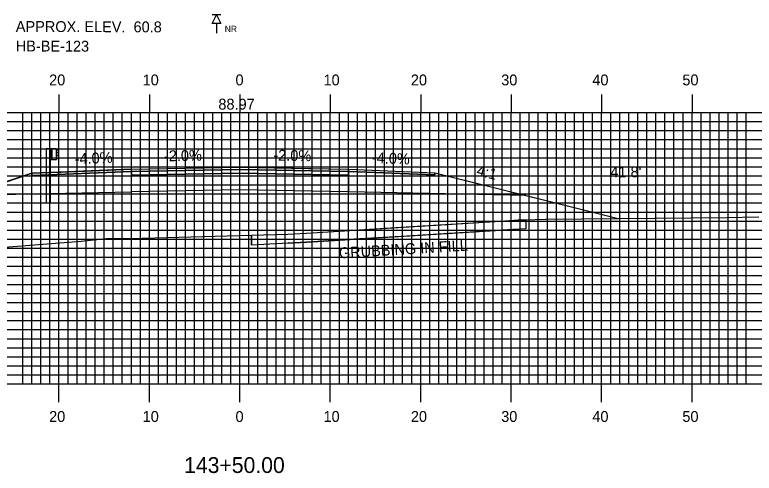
# Model space of a CAD drawing. Extents: x 1777138 to 1777481, y 442591 to 442811.
# Drawn here: x 1777278.9 to 1777360.6, y 442648.8 to 442699.5 of the extents above; entities that cross this region are included whole.
import ezdxf

# ---------------------------------------------------------------- set-up
doc = ezdxf.new("R2010")
doc.units = 0
for name, color, linetype in [('ANNOTATION', 7, 'Continuous'), ('BORING - NO REFUSAL', 7, 'Continuous'), ('D_Guardrail_Beam_Lt', 7, 'Continuous'), ('D_Roadway_Centerline', 7, 'Continuous'), ('D_Roadway_Centerline_Text', 7, 'Continuous'), ('D_Roadway_Edge_Shoulder', 7, 'Continuous'), ('D_Roadway_Edge_TW', 7, 'Continuous'), ('D_Roadway_Pavement', 7, 'Continuous'), ('D_Roadway_SlopeLines', 7, 'Continuous'), ('D_Roadway_SubGrade', 7, 'Continuous'), ('D_Text_Standard', 7, 'Continuous'), ('GRUBBING IN FILL', 7, 'Continuous'), ('H_V ANNOTATION', 7, 'Continuous'), ('MAJOR', 7, 'Continuous'), ('MINOR', 7, 'Continuous'), ('S_Roadway_Centerline', 7, 'Continuous')]:
    doc.layers.add(name, color=color, linetype=linetype)

msp = doc.modelspace()

# ---------------------------------------------------------------- linework, layer by layer
at = {"layer": 'BORING - NO REFUSAL'}
for p, q in [((1777301.644, 442699.465), (1777300.684, 442699.465)), ((1777301.164, 442698.506), (1777301.164, 442697.447))]:
    msp.add_line(p, q, dxfattribs=at)
msp.add_lwpolyline([(1777301.164, 442699.465), (1777301.644, 442698.506), (1777300.684, 442698.506)], close=True, dxfattribs=at)
at = {"layer": 'D_Guardrail_Beam_Lt'}
for p, q in [((1777282.335, 442684.655), (1777282.335, 442678.655)), ((1777282.806, 442684.655), (1777282.335, 442684.655)), ((1777283.493, 442684.655), (1777282.806, 442684.655)), ((1777282.806, 442684.655), (1777282.806, 442683.488)), ((1777282.868, 442684.655), (1777282.868, 442683.488)), ((1777282.973, 442684.655), (1777282.973, 442683.488)), ((1777283.493, 442683.488), (1777283.493, 442684.655)), ((1777283.493, 442684.571), (1777283.568, 442684.557)), ((1777283.498, 442684.106), (1777283.498, 442684.036)), ((1777283.727, 442684.307), (1777283.531, 442684.171)), ((1777283.583, 442684.55), (1777283.727, 442684.45)), ((1777282.806, 442683.488), (1777283.493, 442683.488)), ((1777282.827, 442678.655), (1777282.827, 442683.488)), ((1777283.568, 442683.586), (1777283.493, 442683.571)), ((1777283.531, 442683.972), (1777283.727, 442683.836)), ((1777283.727, 442683.692), (1777283.583, 442683.592)), ((1777282.827, 442678.655), (1777282.335, 442678.655))]:
    msp.add_line(p, q, dxfattribs=at)
for centre, major_axis, start_param, end_param in [((1777283.577, 442684.106), (-0.0789, 0), 5.323254, 6.283185), ((1777283.559, 442684.516), (0.0417, 0), 0.959931, 1.376053), ((1777283.676, 442684.378), (0.0877, 0), 5.323254, 7.243116), ((1777283.577, 442684.036), (-0.0789, 0), 6.283185, 7.243116), ((1777283.559, 442683.626), (0.0417, 0), 4.907132, 5.323254), ((1777283.676, 442683.764), (0.0877, 0), 5.323254, 7.243116)]:
    msp.add_ellipse(centre, major_axis=major_axis, ratio=0.995501, start_param=start_param, end_param=end_param, dxfattribs=at)
at = {"layer": 'D_Roadway_Centerline'}
msp.add_lwpolyline([(1777250.63, 442671.906), (1777264.063, 442676.384), (1777273.487, 442679.526), (1777273.49, 442679.527), (1777276.411, 442680.501), (1777280.764, 442681.951), (1777280.768, 442681.951), (1777283.628, 442682.066), (1777283.764, 442682.071), (1777284.006, 442682.081), (1777291.764, 442682.391), (1777291.787, 442682.392), (1777303.764, 442682.631), (1777303.773, 442682.631), (1777311.355, 442682.479), (1777315.764, 442682.391), (1777325.334, 442682.008), (1777325.336, 442682.008), (1777335.367, 442679.501), (1777335.373, 442679.499), (1777337.335, 442679.009), (1777337.336, 442679.008), (1777345.601, 442676.942)], dxfattribs=at)
at = {"layer": 'D_Roadway_Edge_Shoulder'}
for points in [[(1777291.764, 442682.391), (1777283.764, 442682.071), (1777283.764, 442682.071), (1777280.764, 442681.951), (1777280.764, 442681.701), (1777291.764, 442682.141)], [(1777315.764, 442682.391), (1777325.336, 442682.008), (1777325.336, 442681.758), (1777315.764, 442682.141)]]:
    msp.add_lwpolyline(points, close=True, dxfattribs=at)
at = {"layer": 'D_Roadway_Edge_TW'}
msp.add_lwpolyline([(1777291.764, 442682.141), (1777291.764, 442682.391), (1777303.764, 442682.631), (1777315.764, 442682.391), (1777315.764, 442682.141), (1777303.764, 442682.381)], close=True, dxfattribs=at)
at = {"layer": 'D_Roadway_Pavement'}
msp.add_lwpolyline([(1777291.764, 442681.724), (1777291.764, 442682.141), (1777303.764, 442682.381), (1777315.764, 442682.141), (1777315.764, 442681.724), (1777303.764, 442681.964)], close=True, dxfattribs=at)
for points in [[(1777291.764, 442682.141), (1777291.764, 442681.724)], [(1777315.764, 442682.141), (1777315.764, 442681.724)]]:
    msp.add_lwpolyline(points, dxfattribs=at)
at = {"layer": 'D_Roadway_SlopeLines'}
for points in [[(1777280.764, 442681.951), (1777250.63, 442671.906)], [(1777325.336, 442682.008), (1777337.336, 442679.008), (1777345.601, 442676.942)]]:
    msp.add_lwpolyline(points, dxfattribs=at)
at = {"layer": 'D_Roadway_SubGrade'}
for points in [[(1777291.764, 442681.724), (1777291.764, 442682.141), (1777280.764, 442681.701), (1777280.764, 442681.951), (1777273.487, 442679.526), (1777291.764, 442679.891)], [(1777291.764, 442679.891), (1777291.764, 442682.141), (1777291.764, 442681.724), (1777303.764, 442681.964), (1777315.764, 442681.724), (1777315.764, 442682.141), (1777315.764, 442679.891), (1777303.764, 442680.131)], [(1777315.764, 442681.724), (1777315.764, 442682.141), (1777325.336, 442681.758), (1777325.336, 442682.008), (1777335.373, 442679.499), (1777315.764, 442679.891)]]:
    msp.add_lwpolyline(points, close=True, dxfattribs=at)
at = {"layer": 'GRUBBING IN FILL'}
msp.add_line((1777305.052, 442675.105), (1777305.052, 442673.99), dxfattribs=at)
msp.add_line((1777305.052, 442675.105), (1777305.052, 442673.99), dxfattribs=at)
for points in [[(1777335.373, 442676.807), (1777335.373, 442675.807), (1777333.96, 442675.734), (1777322.221, 442675.013), (1777311.805, 442674.36), (1777309.124, 442674.213), (1777305.052, 442673.99)], [(1777335.373, 442676.807), (1777335.373, 442675.807), (1777333.96, 442675.734), (1777322.221, 442675.013), (1777311.805, 442674.36), (1777309.124, 442674.213), (1777305.052, 442673.99)], [(1777309.124, 442674.213), (1777311.805, 442674.36), (1777332.637, 442675.666), (1777333.96, 442675.734)], [(1777309.124, 442674.213), (1777311.805, 442674.36), (1777332.637, 442675.666), (1777333.96, 442675.734)]]:
    msp.add_lwpolyline(points, dxfattribs=at)
msp.add_lwpolyline([(1777305.052, 442675.105), (1777309.083, 442675.212), (1777311.747, 442675.358), (1777322.163, 442676.011), (1777332.58, 442676.664), (1777334.525, 442676.786), (1777335.245, 442676.8), (1777335.373, 442676.807), (1777335.373, 442675.807), (1777328.091, 442675.373), (1777322.221, 442675.013), (1777317.013, 442674.686), (1777311.805, 442674.36), (1777305.052, 442673.99)], close=True, dxfattribs=at)
msp.add_lwpolyline([(1777305.052, 442675.105), (1777309.083, 442675.212), (1777311.747, 442675.358), (1777322.163, 442676.011), (1777332.58, 442676.664), (1777334.525, 442676.786), (1777335.245, 442676.8), (1777335.373, 442676.807), (1777335.373, 442675.807), (1777328.091, 442675.373), (1777322.221, 442675.013), (1777317.013, 442674.686), (1777311.805, 442674.36), (1777305.052, 442673.99)], close=True, dxfattribs=at)
at = {"layer": 'MAJOR'}
for p, q in [((1777283.764, 442690.669), (1777283.764, 442688.665)), ((1777293.764, 442690.669), (1777293.764, 442688.665)), ((1777303.764, 442690.669), (1777303.764, 442688.665)), ((1777313.764, 442690.669), (1777313.764, 442688.665)), ((1777323.764, 442690.669), (1777323.764, 442688.665)), ((1777333.764, 442690.669), (1777333.764, 442688.665)), ((1777343.764, 442690.669), (1777343.764, 442688.665)), ((1777353.764, 442690.669), (1777353.764, 442688.665)), ((1777163.764, 442688.665), (1777443.764, 442688.665)), ((1777163.764, 442688.665), (1777443.764, 442688.665)), ((1777283.764, 442658.665), (1777283.764, 442688.665)), ((1777293.764, 442658.665), (1777293.764, 442688.665)), ((1777303.764, 442658.665), (1777303.764, 442688.665)), ((1777313.764, 442658.665), (1777313.764, 442688.665)), ((1777323.764, 442658.665), (1777323.764, 442688.665)), ((1777333.764, 442658.665), (1777333.764, 442688.665)), ((1777343.764, 442658.665), (1777343.764, 442688.665)), ((1777353.764, 442658.665), (1777353.764, 442688.665)), ((1777163.764, 442683.665), (1777443.764, 442683.665)), ((1777163.764, 442678.665), (1777443.764, 442678.665)), ((1777163.764, 442673.665), (1777443.764, 442673.665)), ((1777163.764, 442668.665), (1777443.764, 442668.665)), ((1777163.764, 442663.665), (1777443.764, 442663.665)), ((1777163.764, 442658.665), (1777443.764, 442658.665)), ((1777163.764, 442658.665), (1777443.764, 442658.665)), ((1777283.764, 442656.661), (1777283.764, 442658.665)), ((1777293.764, 442656.661), (1777293.764, 442658.665)), ((1777303.764, 442656.661), (1777303.764, 442658.665)), ((1777313.764, 442656.661), (1777313.764, 442658.665)), ((1777323.764, 442656.661), (1777323.764, 442658.665)), ((1777333.764, 442656.661), (1777333.764, 442658.665)), ((1777343.764, 442656.661), (1777343.764, 442658.665)), ((1777353.764, 442656.661), (1777353.764, 442658.665))]:
    msp.add_line(p, q, dxfattribs=at)
at = {"layer": 'MINOR'}
for p, q in [((1777279.764, 442658.665), (1777279.764, 442688.665)), ((1777280.764, 442658.665), (1777280.764, 442688.665)), ((1777281.764, 442658.665), (1777281.764, 442688.665)), ((1777282.764, 442658.665), (1777282.764, 442688.665)), ((1777284.764, 442658.665), (1777284.764, 442688.665)), ((1777285.764, 442658.665), (1777285.764, 442688.665)), ((1777286.764, 442658.665), (1777286.764, 442688.665)), ((1777287.764, 442658.665), (1777287.764, 442688.665)), ((1777288.764, 442658.665), (1777288.764, 442688.665)), ((1777289.764, 442658.665), (1777289.764, 442688.665)), ((1777290.764, 442658.665), (1777290.764, 442688.665)), ((1777291.764, 442658.665), (1777291.764, 442688.665)), ((1777292.764, 442658.665), (1777292.764, 442688.665)), ((1777294.764, 442658.665), (1777294.764, 442688.665)), ((1777295.764, 442658.665), (1777295.764, 442688.665)), ((1777296.764, 442658.665), (1777296.764, 442688.665)), ((1777297.764, 442658.665), (1777297.764, 442688.665)), ((1777298.764, 442658.665), (1777298.764, 442688.665)), ((1777299.764, 442658.665), (1777299.764, 442688.665)), ((1777300.764, 442658.665), (1777300.764, 442688.665)), ((1777301.764, 442658.665), (1777301.764, 442688.665)), ((1777302.764, 442658.665), (1777302.764, 442688.665)), ((1777304.764, 442658.665), (1777304.764, 442688.665)), ((1777305.764, 442658.665), (1777305.764, 442688.665)), ((1777306.764, 442658.665), (1777306.764, 442688.665)), ((1777307.764, 442658.665), (1777307.764, 442688.665)), ((1777308.764, 442658.665), (1777308.764, 442688.665)), ((1777309.764, 442658.665), (1777309.764, 442688.665)), ((1777310.764, 442658.665), (1777310.764, 442688.665)), ((1777311.764, 442658.665), (1777311.764, 442688.665)), ((1777312.764, 442658.665), (1777312.764, 442688.665)), ((1777314.764, 442658.665), (1777314.764, 442688.665)), ((1777315.764, 442658.665), (1777315.764, 442688.665)), ((1777316.764, 442658.665), (1777316.764, 442688.665)), ((1777317.764, 442658.665), (1777317.764, 442688.665)), ((1777318.764, 442658.665), (1777318.764, 442688.665)), ((1777319.764, 442658.665), (1777319.764, 442688.665)), ((1777320.764, 442658.665), (1777320.764, 442688.665)), ((1777321.764, 442658.665), (1777321.764, 442688.665)), ((1777322.764, 442658.665), (1777322.764, 442688.665)), ((1777324.764, 442658.665), (1777324.764, 442688.665)), ((1777325.764, 442658.665), (1777325.764, 442688.665)), ((1777326.764, 442658.665), (1777326.764, 442688.665)), ((1777327.764, 442658.665), (1777327.764, 442688.665)), ((1777328.764, 442658.665), (1777328.764, 442688.665)), ((1777329.764, 442658.665), (1777329.764, 442688.665)), ((1777330.764, 442658.665), (1777330.764, 442688.665)), ((1777331.764, 442658.665), (1777331.764, 442688.665)), ((1777332.764, 442658.665), (1777332.764, 442688.665)), ((1777334.764, 442658.665), (1777334.764, 442688.665)), ((1777335.764, 442658.665), (1777335.764, 442688.665)), ((1777336.764, 442658.665), (1777336.764, 442688.665)), ((1777337.764, 442658.665), (1777337.764, 442688.665)), ((1777338.764, 442658.665), (1777338.764, 442688.665)), ((1777339.764, 442658.665), (1777339.764, 442688.665)), ((1777340.764, 442658.665), (1777340.764, 442688.665)), ((1777341.764, 442658.665), (1777341.764, 442688.665)), ((1777342.764, 442658.665), (1777342.764, 442688.665)), ((1777344.764, 442658.665), (1777344.764, 442688.665)), ((1777345.764, 442658.665), (1777345.764, 442688.665)), ((1777346.764, 442658.665), (1777346.764, 442688.665)), ((1777347.764, 442658.665), (1777347.764, 442688.665)), ((1777348.764, 442658.665), (1777348.764, 442688.665)), ((1777349.764, 442658.665), (1777349.764, 442688.665)), ((1777350.764, 442658.665), (1777350.764, 442688.665)), ((1777351.764, 442658.665), (1777351.764, 442688.665)), ((1777352.764, 442658.665), (1777352.764, 442688.665)), ((1777354.764, 442658.665), (1777354.764, 442688.665)), ((1777355.764, 442658.665), (1777355.764, 442688.665)), ((1777356.764, 442658.665), (1777356.764, 442688.665)), ((1777357.764, 442658.665), (1777357.764, 442688.665)), ((1777358.764, 442658.665), (1777358.764, 442688.665)), ((1777359.764, 442658.665), (1777359.764, 442688.665)), ((1777163.764, 442687.665), (1777443.764, 442687.665)), ((1777163.764, 442686.665), (1777443.764, 442686.665)), ((1777163.764, 442685.665), (1777443.764, 442685.665)), ((1777163.764, 442684.665), (1777443.764, 442684.665)), ((1777163.764, 442682.665), (1777443.764, 442682.665)), ((1777163.764, 442681.665), (1777443.764, 442681.665)), ((1777163.764, 442680.665), (1777443.764, 442680.665)), ((1777163.764, 442679.665), (1777443.764, 442679.665)), ((1777163.764, 442677.665), (1777443.764, 442677.665)), ((1777163.764, 442676.665), (1777443.764, 442676.665)), ((1777163.764, 442675.665), (1777443.764, 442675.665)), ((1777163.764, 442674.665), (1777443.764, 442674.665)), ((1777163.764, 442672.665), (1777443.764, 442672.665)), ((1777163.764, 442671.665), (1777443.764, 442671.665)), ((1777163.764, 442670.665), (1777443.764, 442670.665)), ((1777163.764, 442669.665), (1777443.764, 442669.665)), ((1777163.764, 442667.665), (1777443.764, 442667.665)), ((1777163.764, 442666.665), (1777443.764, 442666.665)), ((1777163.764, 442665.665), (1777443.764, 442665.665)), ((1777163.764, 442664.665), (1777443.764, 442664.665)), ((1777163.764, 442662.665), (1777443.764, 442662.665)), ((1777163.764, 442661.665), (1777443.764, 442661.665)), ((1777163.764, 442660.665), (1777443.764, 442660.665)), ((1777163.764, 442659.665), (1777443.764, 442659.665))]:
    msp.add_line(p, q, dxfattribs=at)
at = {"layer": 'S_Roadway_Centerline'}
msp.add_lwpolyline([(1777230.622, 442670.542), (1777238.5, 442670.852), (1777242.936, 442671.086), (1777246.488, 442671.434), (1777256.648, 442672.594), (1777274.437, 442673.53), (1777286.211, 442674.461), (1777288.983, 442674.722), (1777291.619, 442674.75), (1777309.083, 442675.212), (1777311.747, 442675.358), (1777332.58, 442676.664), (1777335.245, 442676.8), (1777337.55, 442676.863), (1777357.636, 442677.06), (1777359.331, 442677.091), (1777361.141, 442677.142)], dxfattribs=at)

# ---------------------------------------------------------------- texts
at = {"layer": 'ANNOTATION'}
for s, rotation, p in [('-4.0%', 2.29074, (1777285.517, 442682.943)), ('-2.0%', 1.14576, (1777295.381, 442683.264)), ('-2.0%', 358.85424, (1777307.454, 442683.358)), ('-4.0%', 357.70865, (1777318.341, 442683.09)), ('4:1', 345.96561, (1777329.857, 442681.74))]:
    msp.add_text(s, height=1.2, rotation=rotation, dxfattribs=at).set_placement(p)
at = {"layer": 'BORING - NO REFUSAL'}
for s, p in [('APPROX. ELEV.  60.8', (1777278.986, 442697.577)), ('HB-BE-123', (1777278.979, 442695.417))]:
    msp.add_text(s, height=1.2, rotation=359.81416, dxfattribs=at).set_placement(p)
msp.add_text('NR', height=0.6998, dxfattribs=at).set_placement((1777302.096, 442697.55))
at = {"layer": 'D_Roadway_Centerline'}
for s, p in [('C', (1777303.759, 442682.631)), ('L', (1777303.764, 442682.624))]:
    msp.add_text(s, height=0.0146, dxfattribs=at).set_placement(p)
at = {"layer": 'D_Roadway_Centerline_Text'}
msp.add_text('88.97', height=1.2, dxfattribs=at).set_placement((1777301.388, 442688.987))
at = {"layer": 'D_Text_Standard'}
msp.add_text("41.8'", height=1.2, dxfattribs=at).set_placement((1777344.731, 442681.501))
at = {"layer": 'GRUBBING IN FILL'}
msp.add_text('GRUBBING IN FILL', height=1.2, rotation=3.49622, dxfattribs=at).set_placement((1777314.753, 442672.531))
at = {"layer": 'H_V ANNOTATION'}
for s, height, p in [('20', 1.2, (1777282.672, 442691.665)), ('10', 1.2, (1777293.014, 442691.665)), ('0', 1.2, (1777303.282, 442691.665)), ('10', 1.2, (1777313.014, 442691.665)), ('20', 1.2, (1777322.672, 442691.665)), ('30', 1.2, (1777332.661, 442691.665)), ('40', 1.2, (1777342.736, 442691.665)), ('50', 1.2, (1777352.693, 442691.665)), ('20', 1.2, (1777282.672, 442654.465)), ('10', 1.2, (1777293.014, 442654.465)), ('0', 1.2, (1777303.282, 442654.465)), ('10', 1.2, (1777313.014, 442654.465)), ('20', 1.2, (1777322.672, 442654.465)), ('30', 1.2, (1777332.661, 442654.465)), ('40', 1.2, (1777342.736, 442654.465)), ('50', 1.2, (1777352.693, 442654.465)), ('143+50.00', 1.75, (1777297.6, 442648.821))]:
    msp.add_text(s, height=height, dxfattribs=at).set_placement(p)

doc.saveas('drawing.dxf')
